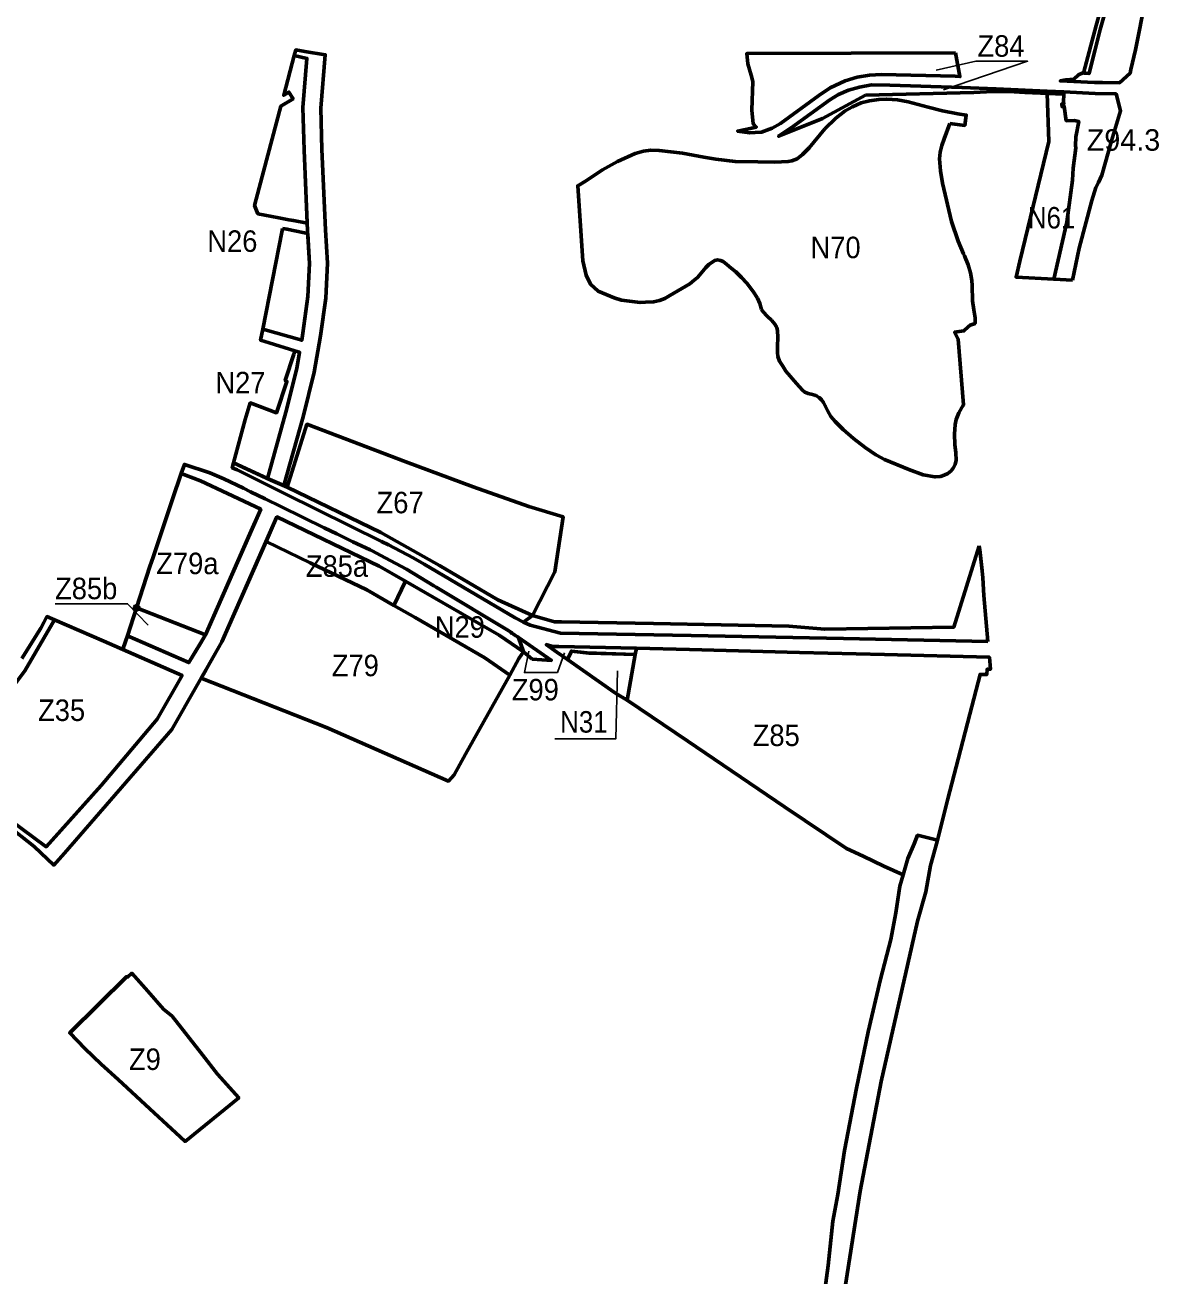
# Model space of a CAD drawing. Extents: x -650277 to -643422, y -1073980 to -1066720.
# Drawn here: x -646242 to -644975, y -1072093 to -1070696 of the extents above; entities that cross this region are included whole.
import ezdxf

# ---------------------------------------------------------------- set-up
doc = ezdxf.new("R2010")
doc.units = 0
doc.header["$LTSCALE"] = 9.6
doc.header["$PDMODE"] = 32
doc.header["$PDSIZE"] = 4.8
for name, color, linetype, lineweight in [('1', 7, 'Continuous', 60), ('11', 7, 'Continuous', 60), ('15', 7, 'Continuous', 60), ('18', 7, 'Continuous', 60), ('20', 7, 'Continuous', 60), ('24', 7, 'Continuous', 60), ('40', 7, 'Continuous', 60), ('45', 7, 'Continuous', 60), ('60', 7, 'Continuous', 60), ('63', 7, 'Continuous', 25)]:
    doc.layers.add(name, color=color, linetype=linetype, lineweight=lineweight)

msp = doc.modelspace()

# ---------------------------------------------------------------- linework, layer by layer
at = {"layer": '1'}
msp.add_lwpolyline([(-646102.04, -1071906.4), (-646068.317, -1071937.555), (-646062.91, -1071942.55), (-646002.93, -1071893.984), (-646026.64, -1071867.44), (-646043.49, -1071845.87), (-646077.32, -1071802.59), (-646087, -1071795), (-646104.5, -1071774.86), (-646122.16, -1071754.78), (-646127.12, -1071759.15), (-646127.84, -1071758.53), (-646191.57, -1071821.44), (-646174.69, -1071838.69), (-646156.59, -1071856.53), (-646137.74, -1071873.31)], close=True, dxfattribs=at)
at = {"layer": '11'}
msp.add_lwpolyline([(-646066.165, -1071422.155), (-646153.5, -1071383.85), (-646208.577, -1071360.044), (-646241.68, -1071416.887), (-646258.487, -1071439.265), (-646275.615, -1071460.886), (-646289.976, -1071477.514), (-646330.914, -1071521.11), (-646324, -1071535), (-646217.978, -1071613.552), (-646211.407, -1071606.247), (-646156.471, -1071545.166), (-646094.063, -1071471.007)], close=True, dxfattribs=at)
at = {"layer": '15'}
for points in [[(-645039.574, -1070675.065), (-645045.493, -1070696.321), (-645059.308, -1070747.712), (-645059.403, -1070749.195), (-645053.21, -1070749.75), (-645052.4, -1070746.427), (-645046.63, -1070722.77), (-645041, -1070700.44), (-645033.53, -1070674.55)], [(-645955.342, -1071233.725), (-645973.324, -1071224.925), (-645989.7, -1071216.91), (-645997.62, -1071213.03), (-646019.41, -1071202.36), (-646035.06, -1071195.87), (-646063.59, -1071186.33), (-646067.097, -1071196.699), (-646045.462, -1071204.917), (-646015.387, -1071218.854), (-645978.403, -1071236.481), (-646040.084, -1071376.813), (-646058.719, -1071407.796), (-646127.301, -1071378.036), (-646131.79, -1071391.83), (-646132.229, -1071393.179), (-646066.165, -1071422.155), (-646094.063, -1071471.007), (-646156.471, -1071545.166), (-646211.407, -1071606.247), (-646217.978, -1071613.552)], [(-645701.44, -1071372.25), (-645782.32, -1071323.5), (-645784.92, -1071321.93), (-645815.65, -1071303.41), (-645839.37, -1071290.6), (-645854.1, -1071282.93), (-645856.26, -1071281.91), (-645875.48, -1071272.81), (-645893.41, -1071264.04), (-645907.62, -1071257.08), (-645955.342, -1071233.725)], [(-646223.928, -1071620.168), (-646209.322, -1071634.004), (-646197.398, -1071620.579), (-646077.593, -1071482.499), (-646021.674, -1071384.575), (-645964.396, -1071254.314), (-645960.34, -1071245.09)], [(-645960.34, -1071245.09), (-645846, -1071300), (-645712, -1071377)], [(-646241.68, -1071416.887), (-646208.577, -1071360.044), (-646217.049, -1071356.382), (-646220.61, -1071363.16), (-646223.77, -1071369.24), (-646245.1, -1071403.04)], [(-645712, -1071377), (-645685.098, -1071395.824), (-645690.677, -1071379.721)], [(-646217.978, -1071613.552), (-646324, -1071535)], [(-646261.46, -1071589.38), (-646231.43, -1071613.06), (-646223.928, -1071620.168)]]:
    msp.add_lwpolyline(points, dxfattribs=at)
for points in [[(-645911.345, -1070788.463), (-645906.373, -1070728.716), (-645929.077, -1070725.068), (-645939.27, -1070723.43), (-645940.955, -1070729.799), (-645926.784, -1070732.812), (-645931.369, -1070787.913), (-645930.036, -1070835.367), (-645926.084, -1070925.481), (-645923.919, -1070961.855), (-645925.626, -1070998.754), (-645931.24, -1071039.686), (-645932.635, -1071047.688), (-645976.17, -1071035.39), (-645978.58, -1071047.68), (-645973.77, -1071049.17), (-645968.97, -1071050.66), (-645940.25, -1071059.59), (-645934.978, -1071061.119), (-645938.15, -1071079.311), (-645950.283, -1071128.057), (-645970.966, -1071202.169), (-645952.419, -1071210.117), (-645930.943, -1071133.161), (-645918.57, -1071083.449), (-645911.474, -1071042.764), (-645905.69, -1071000.578), (-645903.891, -1070961.723), (-645906.11, -1070924.449), (-645910.048, -1070834.649)], [(-645694.15, -1071357.83), (-645684.785, -1071362.539), (-645674.947, -1071355.071), (-645713.428, -1071337.765), (-645778.69, -1071299.362), (-645844.079, -1071262.487), (-645948.761, -1071211.885), (-645967, -1071204), (-646008.714, -1071184.746), (-646010.14, -1071190.08), (-646004.65, -1071192.55), (-645951.118, -1071219.11), (-645843.45, -1071272.53), (-645835.76, -1071276.35), (-645808.13, -1071290.78), (-645795.97, -1071297.93), (-645694.15, -1071357.83)]]:
    msp.add_lwpolyline(points, close=True, dxfattribs=at)
msp.add_arc((-645538.107, -1071148.434), 277.076, 233.87926, 236.5888, dxfattribs=at)
at = {"layer": '18'}
for points in [[(-645678.86, -1071233.58), (-645741.09, -1071211.36), (-645816.47, -1071183.63), (-645926.81, -1071141.595), (-645948.761, -1071211.885)], [(-645948.761, -1071211.885), (-645844.079, -1071262.487), (-645778.69, -1071299.362), (-645713.428, -1071337.765), (-645674.947, -1071355.071)], [(-645674.947, -1071355.071), (-645650.09, -1071306.433), (-645640.737, -1071244.963), (-645678.86, -1071233.58)]]:
    msp.add_lwpolyline(points, dxfattribs=at)
at = {"layer": '20'}
for points in [[(-645990.48, -1071263.958), (-645978.403, -1071236.481), (-646015.387, -1071218.854), (-646045.462, -1071204.917), (-646067.097, -1071196.699), (-646076.713, -1071225.138)], [(-646076.713, -1071225.138), (-646098.66, -1071290.03), (-646102.011, -1071300.326), (-646117.031, -1071346.48)], [(-646117.031, -1071346.48), (-646040.084, -1071376.813), (-645990.48, -1071263.958)]]:
    msp.add_lwpolyline(points, dxfattribs=at)
msp.add_lwpolyline([(-645972.423, -1071272.568), (-646021.674, -1071384.575), (-646039.658, -1071416.067), (-646044.948, -1071425.333), (-645905.027, -1071480.359), (-645768.62, -1071540.17), (-645762.54, -1071533.015), (-645749.631, -1071509.908), (-645700.38, -1071421.746), (-645728.054, -1071402.382), (-645806.036, -1071357.564), (-645829.706, -1071343.963), (-645859.986, -1071326.563), (-645923.023, -1071296.291), (-645972.422, -1071272.568)], close=True, dxfattribs=at)
msp.add_point((-646117.031, -1071346.48), dxfattribs=at)
at = {"layer": '24'}
msp.add_lwpolyline([(-645303, -1070774), (-645182, -1070771), (-645161, -1070770), (-645143, -1070770), (-645125.217, -1070770.81), (-645081.75, -1070772.79), (-645081.6, -1070770.362), (-645100.32, -1070769.5), (-645156.988, -1070766.884), (-645195.527, -1070765.319), (-645195.527, -1070765.319), (-645275.8, -1070762.66), (-645296.51, -1070762.52), (-645309.78, -1070764.88), (-645321.9, -1070768.47), (-645333.12, -1070773.33), (-645342.94, -1070779.31), (-645385.99, -1070810.35), (-645400.05, -1070819.84), (-645351, -1070800)], close=True, dxfattribs=at)
at = {"layer": '40'}
for points in [[(-645926.457, -1070916.969), (-645930.036, -1070835.367), (-645931.369, -1070787.913), (-645926.784, -1070732.812), (-645940.955, -1070729.799), (-645952.65, -1070773.98), (-645946.81, -1070770.47), (-645942.3, -1070777.96), (-645955.86, -1070786.21), (-645980.01, -1070877.28), (-645985.28, -1070897.13), (-645981.48, -1070906.35), (-645958.21, -1070910.84)], [(-645958.21, -1070910.84), (-645946.85, -1070913.03), (-645941.94, -1070913.98), (-645926.457, -1070916.969)], [(-645954.01, -1070922.8), (-645954.492, -1070925.251), (-645976.17, -1071035.39), (-645932.635, -1071047.688), (-645931.24, -1071039.686), (-645925.626, -1070998.754), (-645923.919, -1070961.855), (-645925.908, -1070928.435)], [(-645925.908, -1070928.435), (-645944.08, -1070924.79), (-645948.99, -1070923.81), (-645954.01, -1070922.8)]]:
    msp.add_lwpolyline(points, dxfattribs=at)
for points in [[(-645970.966, -1071202.169), (-645950.283, -1071128.057), (-645938.15, -1071079.311), (-645934.978, -1071061.119), (-645940.25, -1071059.59), (-645941.45, -1071063.3), (-645950.96, -1071092.8), (-645949.21, -1071093.62), (-645960.66, -1071128.71), (-645990.14, -1071117.76), (-645995.74, -1071136.22), (-646008.714, -1071184.746)], [(-645700.38, -1071421.746), (-645690.056, -1071403.266), (-645685.098, -1071395.824), (-645712, -1071377), (-645816.714, -1071316.828), (-645829.706, -1071343.963), (-645806.036, -1071357.564), (-645728.054, -1071402.382)], [(-645583.18, -1071441.3), (-645580.947, -1071442.658), (-645569.07, -1071449.88), (-645560.11, -1071398.7), (-645611.58, -1071397.14), (-645631.44, -1071394.9), (-645635.795, -1071404.403)]]:
    msp.add_lwpolyline(points, close=True, dxfattribs=at)
at = {"layer": '45'}
for points in [[(-645255.407, -1070781.443), (-645267.315, -1070779.162), (-645279.349, -1070778.402), (-645288.343, -1070778.909), (-645298.731, -1070780.176), (-645307.923, -1070782.557), (-645317.677, -1070786.866), (-645325.785, -1070791.428), (-645336.046, -1070799.793), (-645348.318, -1070811.675)], [(-645100.268, -1070771.946), (-645098.438, -1070825.558), (-645130.749, -1070959.561), (-645134.972, -1070977.077), (-645092.67, -1070979.52)], [(-645083.49, -1070786.92), (-645083.95, -1070783.89), (-645081.57, -1070783.53), (-645081.85, -1070781.59), (-645081.75, -1070772.79), (-645100.268, -1070771.946)], [(-645208.696, -1070805.535), (-645192.298, -1070807.665), (-645190.59, -1070796.152), (-645200.111, -1070794.621), (-645217.086, -1070791.58), (-645233.003, -1070787.399), (-645255.407, -1070781.443)], [(-645092.67, -1070979.52), (-645078.23, -1070915.65), (-645071.77, -1070868.73), (-645071.18, -1070855.63), (-645068.07, -1070832.72), (-645068.52, -1070830.52), (-645068.07, -1070820.37), (-645065.01, -1070803.22), (-645070.2, -1070802.33), (-645078.85, -1070802.46), (-645081.13, -1070786.56), (-645083.49, -1070786.92)], [(-645199.714, -1070937.126), (-645206.872, -1070914.991), (-645216.991, -1070872.38), (-645219.351, -1070858.481), (-645220.312, -1070845.02), (-645219.787, -1070837.502), (-645217.778, -1070830.159), (-645215.063, -1070822.589), (-645208.696, -1070805.535)], [(-645348.318, -1070811.675), (-645366.02, -1070832.94), (-645373.241, -1070840.417), (-645379.448, -1070845.106), (-645385.148, -1070847.387), (-645389.329, -1070848.148), (-645404.15, -1070848.781), (-645423.364, -1070848.402)], [(-645560.079, -1070839.137), (-645579.841, -1070848.008), (-645596.689, -1070857.387), (-645615.817, -1070870.187), (-645624.321, -1070875.224), (-645618.798, -1070958.861), (-645615, -1070975), (-645610, -1070985), (-645601.41, -1070992.83)], [(-645507.299, -1070838.899), (-645533.268, -1070835.731), (-645542.642, -1070835.35), (-645550.832, -1070836.602), (-645560.079, -1070839.137)], [(-645470.235, -1070845.487), (-645483.61, -1070843.208), (-645507.299, -1070838.899)], [(-645423.364, -1070848.402), (-645448.7, -1070847.895), (-645470.235, -1070845.487)], [(-645192.548, -1070953.47), (-645193.51, -1070951.2), (-645199.714, -1070937.126)], [(-645481.466, -1070966.271), (-645477.971, -1070963.036), (-645474.301, -1070960.414), (-645471.418, -1070958.578), (-645468.185, -1070957.966), (-645464.865, -1070958.491), (-645462.069, -1070959.89)], [(-645462.069, -1070959.89), (-645457.875, -1070962.949), (-645452.982, -1070967.057), (-645448.001, -1070971.341), (-645441.361, -1070977.635)], [(-645183.833, -1070986.74), (-645184.357, -1070981.146), (-645185.843, -1070972.23), (-645188.377, -1070963.313), (-645192.548, -1070953.47)], [(-645494.223, -1070980.781), (-645490.641, -1070977.722), (-645486.534, -1070972.652), (-645481.466, -1070966.271)], [(-645554.524, -1071005.405), (-645548.534, -1071005.316), (-645539.622, -1071004.966), (-645533.156, -1071003.131), (-645527.302, -1071001.033), (-645521.535, -1070997.886), (-645499.204, -1070984.54), (-645494.223, -1070980.781)], [(-645441.361, -1070977.635), (-645435.443, -1070984.082), (-645428.541, -1070993.348), (-645423.648, -1071000.865)], [(-645180.506, -1071022.778), (-645182.261, -1071013.633), (-645183.746, -1071003.786), (-645183.833, -1070986.74)], [(-645601.41, -1070992.83), (-645583.707, -1071000.16), (-645575.406, -1071002.782), (-645563.698, -1071004.618), (-645554.524, -1071005.405)], [(-645423.648, -1071000.865), (-645421.21, -1071006.61), (-645419.026, -1071013.254)], [(-645419.026, -1071013.254), (-645417.453, -1071016.051), (-645412.735, -1071020.771), (-645407.492, -1071025.841)], [(-645407.492, -1071025.841), (-645404.172, -1071029.687), (-645402.194, -1071033.492), (-645401.408, -1071037.251), (-645400.796, -1071044.157), (-645401.233, -1071054.647)], [(-645202.951, -1071141.698), (-645201.648, -1071136.226), (-645198.678, -1071128.971), (-645198.678, -1071128.971), (-645193.872, -1071120.142), (-645193.872, -1071120.142), (-645193.592, -1071119.776), (-645199.57, -1071046.58), (-645203.66, -1071038.81), (-645193.24, -1071037.31), (-645188.39, -1071032.86), (-645186.18, -1071030.83), (-645180.72, -1071028.86), (-645180.506, -1071022.778)], [(-645401.233, -1071054.647), (-645401.408, -1071061.465), (-645400.796, -1071065.748), (-645398.979, -1071070.938), (-645395.234, -1071076.602), (-645395.222, -1071076.62), (-645391.902, -1071082.302)], [(-645391.902, -1071082.302), (-645380.193, -1071095.851), (-645373.291, -1071103.543), (-645370.698, -1071105.6), (-645367.028, -1071107.348), (-645362.223, -1071108.484), (-645358.326, -1071109.586), (-645358.203, -1071109.621)], [(-645358.203, -1071109.621), (-645354.883, -1071111.631), (-645352, -1071114.429), (-645349.99, -1071117.401)], [(-645349.99, -1071117.401), (-645347.631, -1071121.771), (-645345.097, -1071126.754)], [(-645345.097, -1071126.754), (-645341.689, -1071132.873), (-645336.884, -1071138.467), (-645328.059, -1071147.471), (-645316.308, -1071157.576), (-645303.551, -1071167.541), (-645291.581, -1071175.845), (-645290.83, -1071176.217), (-645281.707, -1071180.74)], [(-645211.07, -1071196.464), (-645207.575, -1071193.492), (-645205.049, -1071190.531), (-645202.777, -1071186.423), (-645201.903, -1071181.615), (-645202.34, -1071173.66), (-645203.301, -1071164.132), (-645203.738, -1071152.537), (-645202.951, -1071141.698)], [(-645281.707, -1071180.74), (-645254.845, -1071191.919), (-645238.506, -1071198.212)], [(-645238.506, -1071198.212), (-645225.487, -1071200.398), (-645225.487, -1071200.398), (-645219.283, -1071199.786), (-645215.351, -1071198.562), (-645211.07, -1071196.464)]]:
    msp.add_lwpolyline(points, dxfattribs=at)
at = {"layer": '60'}
for points in [[(-645033.53, -1070674.55), (-645041, -1070700.44), (-645046.63, -1070722.77), (-645052.4, -1070746.427), (-645053.21, -1070749.75), (-645060.46, -1070749.1), (-645065.17, -1070751.39), (-645070.3, -1070755.92), (-645079.38, -1070756.91), (-645085.58, -1070758.04), (-645047.39, -1070759.71), (-645038.44, -1070759.83), (-645019.57, -1070760.07), (-645007.68, -1070749.5), (-645006.739, -1070745.384), (-645001.71, -1070723.39), (-644997.14, -1070700.88), (-644992.6, -1070677.92)], [(-645071.99, -1070980.72), (-645064.39, -1070944.7), (-645050.47, -1070891.48), (-645045.74, -1070877.19), (-645043, -1070871.35), (-645039.25, -1070863.33), (-645028.25, -1070824.83), (-645018.18, -1070791.34), (-645023.25, -1070772.62), (-645046.46, -1070771.98), (-645081.6, -1070770.362), (-645081.75, -1070772.79), (-645081.85, -1070781.59), (-645081.57, -1070783.53)], [(-645081.57, -1070783.53), (-645083.95, -1070783.89), (-645083.49, -1070786.92), (-645081.13, -1070786.56), (-645078.85, -1070802.46), (-645070.2, -1070802.33)], [(-645070.2, -1070802.33), (-645065.01, -1070803.22), (-645068.07, -1070820.37)], [(-645068.07, -1070820.37), (-645068.52, -1070830.52), (-645068.07, -1070832.72), (-645071.18, -1070855.63), (-645071.77, -1070868.73), (-645078.23, -1070915.65)], [(-645078.23, -1070915.65), (-645092.67, -1070979.52), (-645071.99, -1070980.72)], [(-645176.14, -1071277.26), (-645204.341, -1071368.19), (-645348.55, -1071370.559), (-645388.619, -1071366.991), (-645539.738, -1071364.092), (-645642.431, -1071362.259), (-645650.28, -1071362.07), (-645674.947, -1071355.071), (-645684.785, -1071362.539), (-645677.58, -1071366.16), (-645643.56, -1071374.75), (-645497.84, -1071377.53), (-645327.76, -1071380.76), (-645166.34, -1071384.07)], [(-645166.34, -1071384.07), (-645170.91, -1071332.86), (-645172.03, -1071312.96), (-645172.85, -1071305.45), (-645175.4, -1071281.93), (-645175.67, -1071279.45), (-645176.14, -1071277.26)], [(-645222.48, -1071606.08), (-645244.81, -1071600.61), (-645248.786, -1071610.383), (-645255.662, -1071626.67)], [(-645339.904, -1072462.677), (-645347.551, -1072443.527), (-645347.677, -1072391.355), (-645346.62, -1072330.914), (-645343.458, -1072278.998), (-645339.908, -1072235.158), (-645335.367, -1072185.207), (-645325.498, -1072102.789), (-645309.01, -1071998.147), (-645285.617, -1071875.733), (-645244.798, -1071696.585), (-645235.793, -1071663.703), (-645230.436, -1071634.261), (-645227.905, -1071625.277), (-645222.48, -1071606.08)], [(-645255.662, -1071626.67), (-645261.094, -1071645.025), (-645264.841, -1071657.687), (-645269.077, -1071687.396), (-645274.868, -1071717.176), (-645286.175, -1071761.228), (-645300.076, -1071820.179), (-645313.153, -1071883.081)], [(-645313.153, -1071883.081), (-645326.343, -1071952.807), (-645334.118, -1072001.954), (-645339.455, -1072031.565), (-645344.819, -1072081.225), (-645351.358, -1072130.815), (-645361.317, -1072232.824), (-645364.435, -1072280.268), (-645366.951, -1072331.609), (-645370.624, -1072401.447), (-645372.228, -1072438.764)]]:
    msp.add_lwpolyline(points, dxfattribs=at)
for points in [[(-645202.41, -1070726.571), (-645197.539, -1070753.128), (-645202.96, -1070752.89), (-645285.11, -1070750.69), (-645298.41, -1070751.48), (-645312.2, -1070753.77), (-645325.82, -1070757.94), (-645342.41, -1070765.76), (-645354.98, -1070774.28), (-645398.04, -1070805.44), (-645407.37, -1070810.95), (-645419.18, -1070815.44), (-645426.36, -1070815.78), (-645432.07, -1070816.05), (-645445.81, -1070814.06), (-645429.993, -1070810.647), (-645424.969, -1070809.563), (-645428.39, -1070806.09), (-645430, -1070790.68), (-645428.73, -1070758.67), (-645430.84, -1070751.43), (-645434.53, -1070738.77), (-645435.711, -1070727.497)], [(-645303, -1070774), (-645182, -1070771), (-645161, -1070770), (-645143, -1070770), (-645125.217, -1070770.81), (-645081.75, -1070772.79), (-645081.6, -1070770.362), (-645100.32, -1070769.5), (-645156.988, -1070766.884), (-645195.527, -1070765.319), (-645195.527, -1070765.319), (-645275.8, -1070762.66), (-645296.51, -1070762.52), (-645309.78, -1070764.88), (-645321.9, -1070768.47), (-645333.12, -1070773.33), (-645342.94, -1070779.31), (-645385.99, -1070810.35), (-645400.05, -1070819.84), (-645351, -1070800)], [(-645816.714, -1071316.828), (-645846, -1071300), (-645960.34, -1071245.09), (-645964.396, -1071254.314), (-645972.422, -1071272.568), (-645972.422, -1071272.568), (-645923.023, -1071296.291), (-645859.986, -1071326.563), (-645829.705, -1071343.962)], [(-646045.393, -1071385.64), (-646040.084, -1071376.813), (-646117.031, -1071346.48), (-646127.301, -1071378.036), (-646058.719, -1071407.796)], [(-645675.177, -1071403.922), (-645675.177, -1071403.922), (-645653.742, -1071405.36), (-645690.677, -1071379.721), (-645685.098, -1071395.824)], [(-645614.201, -1071396.844), (-645560.11, -1071398.7), (-645558.872, -1071391.801), (-645558.9, -1071391.8), (-645645.368, -1071389.96), (-645651.93, -1071389.82), (-645659.6, -1071387.71), (-645647.727, -1071396.036), (-645635.795, -1071404.403), (-645631.44, -1071394.9)], [(-645560.11, -1071398.7), (-645569.07, -1071449.88), (-645501.37, -1071495.68), (-645393.34, -1071568.75), (-645324.17, -1071615.53), (-645324.17, -1071615.53), (-645305.78, -1071624.13), (-645282.54, -1071634.997), (-645261.094, -1071645.025), (-645255.662, -1071626.67), (-645248.786, -1071610.383), (-645244.81, -1071600.61), (-645222.48, -1071606.08), (-645222.48, -1071606.08), (-645211.27, -1071560.01), (-645199.61, -1071515.68), (-645186.67, -1071465.55), (-645175.06, -1071420.93), (-645167.58, -1071421.19), (-645167.37, -1071415.2), (-645163.56, -1071415.3), (-645164.76, -1071401.79), (-645281.92, -1071398.82), (-645376.87, -1071396.41), (-645499.65, -1071393.3), (-645558.9, -1071391.8), (-645645.368, -1071389.96), (-645651.93, -1071389.82), (-645659.6, -1071387.71), (-645647.727, -1071396.036), (-645635.795, -1071404.403), (-645631.44, -1071394.9), (-645614.201, -1071396.844)]]:
    msp.add_lwpolyline(points, close=True, dxfattribs=at)
at = {"layer": '63'}
msp.add_line((-645647, -1071419), (-645639, -1071397), dxfattribs=at)
for points in [[(-645224, -1070746), (-645180, -1070736), (-645122, -1070736), (-645216, -1070768)], [(-646208, -1071342), (-646127, -1071342), (-646104, -1071366)], [(-645647, -1071419), (-645684, -1071419), (-645679, -1071395)], [(-645650, -1071493), (-645582, -1071493), (-645580, -1071417)]]:
    msp.add_lwpolyline(points, dxfattribs=at)

# ---------------------------------------------------------------- texts
for s, width, p in [('Z84', 0.95, (-645178, -1070731)), ('N61', 0.9, (-645121.693, -1070922.874)), ('N26', 0.95, (-646038, -1070949)), ('N70', 0.95, (-645364.436, -1070956.045)), ('N27', 0.95, (-646029, -1071107)), ('Z67', 0.95, (-645849, -1071241)), ('Z79a', 0.95, (-646095, -1071309)), ('Z85a', 0.95, (-645928, -1071312)), ('Z85b', 0.95, (-646208, -1071337)), ('N29', 0.95, (-645784, -1071380)), ('Z79', 0.95, (-645899, -1071423)), ('Z99', 0.95, (-645698, -1071450)), ('Z35', 0.95, (-646227, -1071473)), ('N31', 0.9, (-645644, -1071486)), ('Z85', 0.95, (-645429, -1071501)), ('Z9', 0.95, (-646125.48, -1071862.818))]:
    msp.add_text(s, height=24, dxfattribs=dict(at, width=width)).set_placement(p)
msp.add_text('Z94.3', height=24, dxfattribs=at).set_placement((-645056, -1070836))

doc.saveas('drawing.dxf')
